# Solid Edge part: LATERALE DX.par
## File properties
Subject: LATERALE DX
Author: f_grande
Template: Normal.par
Last saved by: f_grande
Revision: 20
Application: Solid Edge
Material: MDF
Stile della faccia: Marroncino
Coef. of Thermal Exp: 0.0
Thermal Conductivity: 0.0
Specific Heat: 0.0
Modulus of Elasticity: 0.0
Poisson's Ratio: 0.0
Yield Stress: 0.0
Ultimate Stress: 0.0
Elongation: 0.0
Tipo di contenuto documento: 0
Densità: 750,000 kg/m^3
Precisione: 0,990
Document Number: KR0116
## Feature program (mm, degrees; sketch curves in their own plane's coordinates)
sketch for "unnamed Protrusion 1" plane through (0, 0, 0) normal (0, -1, 0) x-axis (1, 0, 0)
  line (-31.1402, -42.2949) -> (158.8598, -42.2949)
  line (158.8598, 45.2051) -> (158.8598, -42.2949)
  line (158.8598, 45.2051) -> (41.5285, 477.7051)
  line (41.5285, 477.7051) -> (-45.4715, 477.7051)
  line (-106.4715, 384.7051) -> (-45.4715, 477.7051)
  line (-106.4715, 384.7051) -> (-106.4715, 314.7051)
  line (-106.4715, 314.7051) -> (-31.1402, 198.7051)
  line (-31.1402, -42.2949) -> (-31.1402, 198.7051)
  dimension (linear) = 31.1402
  dimension (linear) = 41.5285
  dimension (linear) = 106.4715
  dimension (linear) = 158.8598
  dimension (linear) = 31.1402
  dimension (linear) = 106.4715
extrude "unnamed Protrusion 1" add finite 19 along +normal
sketch for "Foro_1" plane through (25.7098, -19, 217.2051) normal (0, -1, 0) x-axis (1, 0, 0)
  hole centre (-98.7813, 132.5) bore radius 10
hole "Foro_1" diameter 20 through
sketch for "Foro_8" plane through (25.7098, 0, 217.2051) normal (0, 1, 0) x-axis (-1, 0, 0)
hole "Foro_8" diameter 9 through  CounterSinkAngle = 82 deg
sketch for "unnamed Hole 1" plane through (25.7098, 0, 217.2051) normal (0, 1, 0) x-axis (-1, 0, 0)
hole "unnamed Hole 1" through
sketch for "unnamed Hole 2" plane through (25.7098, 0, 217.2051) normal (0, 1, 0) x-axis (-1, 0, 0)
  hole centre (-15.6, -203.9) bore radius 4.5
hole "unnamed Hole 2" through
sketch for "unnamed Hole 3" plane through (25.7098, 0, 217.2051) normal (0, 1, 0) x-axis (-1, 0, 0)
hole "unnamed Hole 3" through
pattern "unnamed Pattern 1" of "Foro_8", "unnamed Hole 1", "unnamed Hole 2", "unnamed Hole 3"
sketch for "Foro_12" plane through (25.7098, 0, 217.2051) normal (0, 1, 0) x-axis (-1, 0, 0)
hole "Foro_12" diameter 9 through  CounterSinkAngle = 82 deg
sketch for "unnamed Hole 4" plane through (25.7098, 0, 217.2051) normal (0, 1, 0) x-axis (-1, 0, 0)
hole "unnamed Hole 4" through
pattern "unnamed Pattern 2" of "Foro_12", "unnamed Hole 4"
fillet "Rotondo_4" radius 50
sketch for "Foro_14" plane through (26.1942, 0, 217.7051) normal (0, 1, 0) x-axis (-1, 0, 0)
  hole centre (122.8356, 155.57) bore radius 2.5
hole "Foro_14" diameter 5 through
sketch for "unnamed Hole 5" plane through (26.1942, 0, 217.7051) normal (0, 1, 0) x-axis (-1, 0, 0)
hole "unnamed Hole 5" through
sketch for "unnamed Hole 6" plane through (26.1942, 0, 217.7051) normal (0, 1, 0) x-axis (-1, 0, 0)
  hole centre (122.8356, 108.43) bore radius 2.5
hole "unnamed Hole 6" through
sketch for "unnamed Hole 7" plane through (26.1942, 0, 217.7051) normal (0, 1, 0) x-axis (-1, 0, 0)
  hole centre (75.6956, 155.57) bore radius 2.5
hole "unnamed Hole 7" through
pattern "unnamed Pattern 3" of "Foro_14", "unnamed Hole 5", "unnamed Hole 6", "unnamed Hole 7"
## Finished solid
Body 1: solid body, 28 faces, 55 edges, 18 vertices.
  Faces by surface: cylinder 12, plane 10, cone 6
  Edges by curve: circle 30, line 25
Bounding box of the edges (mm): 265.331 x 19.000 x 520.000, from (-106.4715, -19, -42.2949) to (158.8598, 0, 477.7051).
Cylindrical faces by radius (mm): R2.5 x4, R4.5 x6, R10 x1, R50 x1
Conical faces (half-angle, radius in mm at the cone's reference point): 41 deg R8.5 x6
Planar faces by outward normal: +x 1, +y 1, +z 1, -x 2, -y 1, -z 1, oblique 3
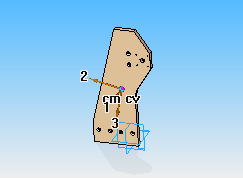
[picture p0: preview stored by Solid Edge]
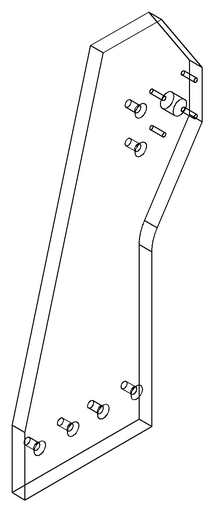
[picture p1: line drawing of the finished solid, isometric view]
